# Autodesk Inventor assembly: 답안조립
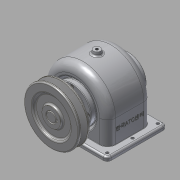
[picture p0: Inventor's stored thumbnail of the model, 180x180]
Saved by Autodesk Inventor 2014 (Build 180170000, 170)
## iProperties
Created: 2015-09
Part Number: 답안조립
Document SubType Name: Assembly
Designer: Owner
Author: Owner
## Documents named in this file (14)
- C:\Documents and Settings\Owner\바탕 화면\450907V1026\답안조립.iam
- C:\Documents and Settings\Owner\바탕 화면\450907V1026\본체.ipt
- C:\Documents and Settings\Owner\바탕 화면\450907V1026\V-벨트풀리.ipt
- C:\Documents and Settings\Owner\바탕 화면\450907V1026\뒤커버.ipt
- C:\Documents and Settings\Owner\바탕 화면\450907V1026\멈춤나사 - M4x10.ipt
- C:\Documents and Settings\Owner\바탕 화면\450907V1026\베어링 6203.ipt
- C:\Documents and Settings\Owner\바탕 화면\450907V1026\볼트 M3 x 8.ipt
- C:\Documents and Settings\Owner\바탕 화면\450907V1026\볼트 M3 x 10.ipt
- C:\Documents and Settings\Owner\바탕 화면\450907V1026\스퍼기어.ipt
- C:\Documents and Settings\Owner\바탕 화면\450907V1026\앞커버.ipt
- C:\Documents and Settings\Owner\바탕 화면\450907V1026\오일 실 17 32 8.ipt
- C:\Documents and Settings\Owner\바탕 화면\450907V1026\축.ipt
- C:\Documents and Settings\Owner\바탕 화면\450907V1026\키 - 5 x 5 x 18.ipt
- C:\Documents and Settings\Owner\바탕 화면\450907V1026\키 - 6 x 6 x 22.ipt
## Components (9 placed, 3 different names)
1. V-벨트풀리:1 — 플러쉬:1
2. ISO 4762 M3 x 8:1
3. ISO 4762 M3 x 8:2
4. ISO 4762 M3 x 8:3
5. ISO 4762 M3 x 8:4
6. ISO 4762 M3 x 10:1
7. ISO 4762 M3 x 10:2
8. ISO 4762 M3 x 10:3
9. ISO 4762 M3 x 10:4
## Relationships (1: Flush 1)
- 플러쉬:1 [Flush]: V-벨트풀리:1
